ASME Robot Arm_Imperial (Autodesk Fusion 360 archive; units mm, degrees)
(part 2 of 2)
sketch "Sketch1" plane through (0, 0, 0) normal (0, 1, 0) x axis (1, 0, 0)
  line L1 (-3.175, 9.525) -> (-3.175, 0)
  line L2 (0, 9.525) -> (-3.175, 9.525)
  line L3 (0, -6.35) -> (0, 9.525)
  line L4 (-4.7625, 0) -> (-3.175, 0)
  line L5 (-4.7625, -6.35) -> (-4.7625, 0)
  line L6 (0, -6.35) -> (-4.7625, -6.35)
  point P1 (0, 0)
  point P4 (0, 9.525)
  point P7 (0, -6.35)
  point P5 (-4.7625, 0)
  point P6 (-4.7625, -6.35)
  perpendicular L1 L2
  collinear P1 P4 P7
  perpendicular L1 L4
  coincident P1 L4
  vertical L1
  vertical L3
  parallel L3 L5
  coincident L3 P7
  perpendicular L3 L6
  dimension "d9" = 6.35 (= "adsk_nomdia")
  dimension "d66" = 9.525 (= "adsk_headdia")
  dimension "d68" distance P1 P4 = 9.525 (= "adsk_nomlen")
  dimension "d79" distance P5 P6 = 6.35 (= "adsk_headh")
revolve "Revolve1" sketch "Sketch1" AlongAngle 360
work_plane "WorkPlane1" AlongDistance 6.35 (= "adsk_headh")
sketch "Sketch6" plane through (0, 0, 6.35) normal (0, 0, 1) x axis (1, 0, 0)
  line L1 (2.3876, 0) -> (-2.3876, 0)
  line L2 (-2.3876, 1.3785) -> (0, 0)
  line L3 (-2.3876, 1.3785) -> (-2.3876, -1.3785)
  line L4 (0, 0) -> (-2.3876, -1.3785)
  point P1 (0, 0)
  point P4 (0, 0)
  point P2 (-2.3876, 0)
  point P5 (-2.3876, 1.3785)
  point P7 (-2.3876, 1.3785)
  point P8 (0, 0)
  point P3 (2.3876, 0)
  horizontal L1
  midpoint P1 L1
  coincident P1 P4
  perpendicular L1 L3
  midpoint P2 L3
  coincident P5 P7
  coincident P1 P8
  dimension "d72" distance P2 P3 = 4.7752 (= "adsk_philwidth")
  dimension "d106" angle L1 L2 = 150
extrude "Extrude1" cut sketch "Sketch6" profile of L2 L3 L4 no distance stored
circular_pattern "C-Pattern1" TotalAngle 360
extrude "Extrude2" cut of existing geometry no distance stored taper -85
thread "Thread2" ThreadOffset 0 ThreadLength 8.1641 (= "adsk_thrlen")
fillet "Fillet4" radius 0.635 (= "adsk_nomdia * 0.1")
sketch "Sketch7" plane through (0, 0, 0) normal (0, 1, 0) x axis (1, 0, 0)
  line L1 (-3.2385, 8.984) -> (-3.2385, 9.525)
  line L2 (-2.634, 9.525) -> (-3.2385, 8.984)
  line L3 (0, -6.35) -> (0, 9.525)
  line L4 (0, 9.525) -> (-3.2385, 9.525)
  point P5 (0, 9.525)
  point P7 (0, 9.525)
  point P4 (-2.634, 9.525)
  point P1 (0, 0)
  point P3 (-3.2385, 8.984)
  coincident P5 P7
  perpendicular L3 L4
  coincident P4 L4
  perpendicular L1 L4
  dimension "d103" distance P1 L1 = 3.2385 (= "adsk_nomdia * 0.51")
  dimension "d104" distance P3 P4 = 0.541 (= "adsk_startlen")
  dimension "d105" distance P1 P4 = 2.634 (= "adsk_endpointdia / 2")
revolve "Revolve3" sketch "Sketch7" AlongAngle 360
joint_origin "JointOrigin2" OffsetX 0 OffsetY 0 OffsetZ 0 AngleZ 0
